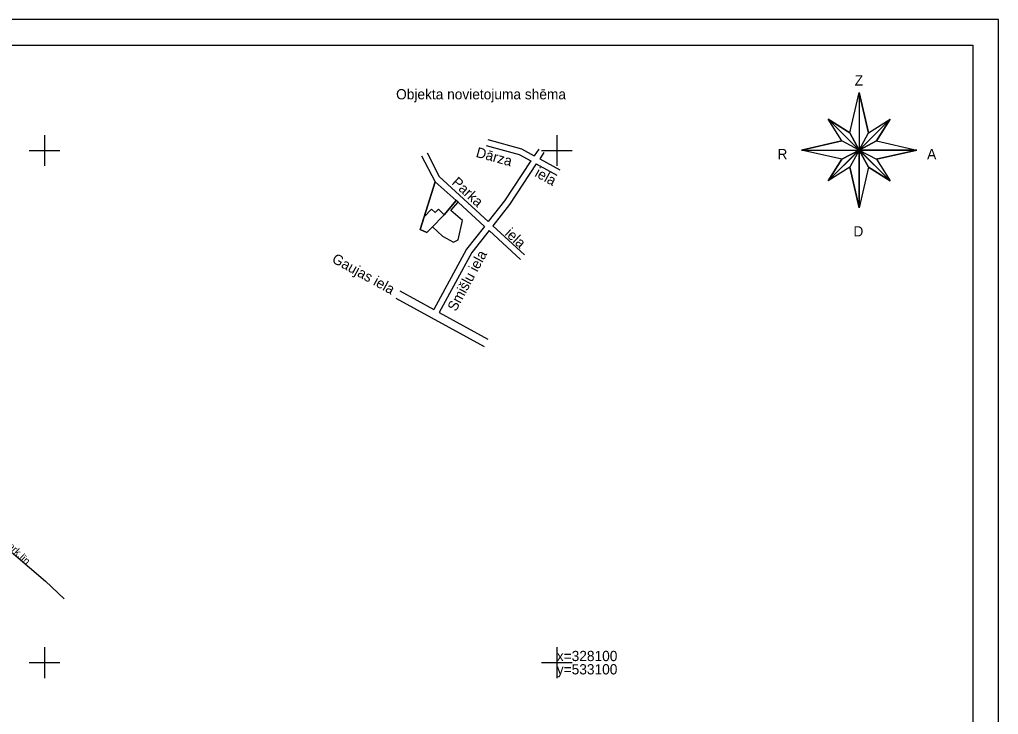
# Model space of a CAD drawing. Extents: x 532933 to 533143, y 328014 to 328163.
# Drawn here: x 533047.6 to 533143.1, y 328094.9 to 328162.8 of the extents above; entities that cross this region are included whole.
import ezdxf

# ---------------------------------------------------------------- set-up
doc = ezdxf.new("R2010")
doc.units = 0
for name, color, linetype in [('APGR_SARK_####_TKST_#', 7, 'Continuous'), ('GEOD_ELEM_####_####_#', 7, 'Continuous'), ('GEOD_KORD_####_TKST_#', 7, 'Continuous'), ('RAMI_PLAN_####_TKST_#', 7, 'Continuous'), ('ROBZ_PROJ_####_####_#', 7, 'Continuous')]:
    doc.layers.add(name, color=color, linetype=linetype)

msp = doc.modelspace()

# ---------------------------------------------------------------- linework, layer by layer
at = {"layer": 'GEOD_ELEM_####_####_#'}
for p, q in [((533050, 328151.5), (533050, 328150)), ((533100, 328151.5), (533100, 328150)), ((533048.5, 328150), (533050, 328150)), ((533050, 328150), (533050, 328148.5)), ((533050, 328150), (533051.5, 328150)), ((533098.5, 328150), (533100, 328150)), ((533100, 328150), (533100, 328148.5)), ((533100, 328150), (533101.5, 328150)), ((533050, 328101.5), (533050, 328100)), ((533100, 328101.5), (533100, 328100)), ((533048.5, 328100), (533050, 328100)), ((533050, 328100), (533050, 328098.5)), ((533050, 328100), (533051.5, 328100)), ((533098.5, 328100), (533100, 328100)), ((533100, 328100), (533100, 328098.5)), ((533100, 328100), (533101.5, 328100))]:
    msp.add_line(p, q, dxfattribs=at)
at = {"layer": 'RAMI_PLAN_####_TKST_#'}
for p, q in [((533143.097, 328162.773), (532933.097, 328162.773)), ((533143.097, 328014.273), (533143.097, 328162.773)), ((532943.097, 328160.273), (533140.597, 328160.273)), ((533140.597, 328160.273), (533140.597, 328016.773)), ((533128.605, 328151.721), (533129.503, 328155.661)), ((533129.503, 328155.661), (533129.503, 328144.411)), ((533129.503, 328155.661), (533130.402, 328151.721)), ((533132.519, 328153.052), (533126.487, 328147.02)), ((533126.487, 328153.052), (533132.519, 328147.02)), ((533127.818, 328150.935), (533126.487, 328153.052)), ((533126.487, 328153.052), (533128.605, 328151.721)), ((533130.402, 328151.721), (533132.519, 328153.052)), ((533132.519, 328153.052), (533131.188, 328150.935)), ((533128.605, 328151.721), (533129.503, 328150.036)), ((533129.503, 328150.036), (533130.402, 328151.721)), ((533123.878, 328150.036), (533127.818, 328150.935)), ((533129.503, 328150.036), (533127.818, 328150.935)), ((533131.188, 328150.935), (533129.503, 328150.036)), ((533131.188, 328150.935), (533135.128, 328150.036)), ((533086.804, 328149.474), (533088.119, 328146.934)), ((533087.336, 328149.75), (533088.521, 328147.463)), ((533123.878, 328150.036), (533135.128, 328150.036)), ((533127.818, 328149.138), (533123.878, 328150.036)), ((533127.818, 328149.138), (533129.503, 328150.036)), ((533129.503, 328150.036), (533128.605, 328148.351)), ((533130.402, 328148.351), (533129.503, 328150.036)), ((533129.503, 328150.036), (533131.188, 328149.138)), ((533135.128, 328150.036), (533131.188, 328149.138)), ((533126.487, 328147.02), (533127.818, 328149.138)), ((533131.188, 328149.138), (533132.519, 328147.02)), ((533128.605, 328148.351), (533126.487, 328147.02)), ((533129.503, 328144.411), (533128.605, 328148.351)), ((533130.402, 328148.351), (533129.503, 328144.411)), ((533132.519, 328147.02), (533130.402, 328148.351)), ((533093.314, 328143.057), (533088.521, 328147.463)), ((533092.942, 328142.584), (533090.362, 328144.955)), ((533096.455, 328139.354), (533093.385, 328142.177)), ((533096.861, 328139.795), (533093.757, 328142.649)), ((533084.672, 328136.29), (533088.006, 328134.461)), ((533084.287, 328135.589), (533092.897, 328130.866)), ((533088.532, 328134.173), (533093.282, 328131.567))]:
    msp.add_line(p, q, dxfattribs=at)
for points in [[(533048.097, 328160.273), (533140.597, 328160.273)], [(533140.597, 328160.273), (533140.597, 328054.273)], [(533129.503, 328150.036), (533130.402, 328151.721), (533129.503, 328155.661), (533129.503, 328150.036)], [(533129.503, 328150.036), (533128.605, 328151.721), (533126.487, 328153.052), (533129.503, 328150.036)], [(533131.188, 328150.935), (533132.519, 328153.052), (533129.503, 328150.036), (533131.188, 328150.935)], [(533093.119, 328150.481), (533096.331, 328149.6), (533097.471, 328148.973)], [(533093.278, 328151.06), (533096.558, 328150.16), (533097.802, 328149.475)], [(533129.503, 328150.036), (533127.818, 328150.935), (533123.878, 328150.036), (533129.503, 328150.036)], [(533098.237, 328150.135), (533097.802, 328149.475)], [(533098.738, 328149.805), (533098.329, 328149.185)], [(533129.503, 328150.036), (533127.818, 328149.138), (533126.487, 328147.02), (533129.503, 328150.036)], [(533129.503, 328150.036), (533128.605, 328148.351), (533129.503, 328144.411), (533129.503, 328150.036)], [(533135.128, 328150.036), (533129.503, 328150.036), (533131.188, 328149.138), (533135.128, 328150.036)], [(533129.503, 328150.036), (533130.402, 328148.351), (533132.519, 328147.02), (533129.503, 328150.036)], [(533097.471, 328148.973), (533094.898, 328145.068), (533093.314, 328143.057)], [(533097.998, 328148.683), (533095.385, 328144.717), (533093.757, 328142.649)], [(533097.998, 328148.683), (533100.002, 328147.579)], [(533098.329, 328149.185), (533100.292, 328148.105)], [(533087.869, 328142.548), (533087.307, 328141.972), (533086.652, 328142.283), (533088.119, 328146.934), (533090.194, 328145.104), (533088.999, 328143.723), (533088.449, 328144.26), (533088.123, 328143.926), (533087.773, 328144.266), (533087.045, 328143.529)], [(533087.869, 328142.548), (533088.836, 328141.634), (533089.925, 328141.047), (533090.363, 328141.258), (533090.801, 328143.162), (533089.651, 328144.133), (533090.362, 328144.955), (533090.194, 328145.104)], [(533088.999, 328143.723), (533088.868, 328143.572), (533087.869, 328142.548)], [(533092.942, 328142.584), (533091.194, 328140.364), (533088.006, 328134.461)], [(533093.385, 328142.177), (533091.697, 328140.033), (533088.532, 328134.173)]]:
    msp.add_lwpolyline(points, dxfattribs=at)
for points in [[(533087.045, 328143.529), (533087.773, 328144.266), (533088.123, 328143.926), (533088.449, 328144.26), (533088.999, 328143.723), (533090.194, 328145.104), (533088.119, 328146.934), (533087.045, 328143.529)], [(533088.868, 328143.572), (533087.869, 328142.548), (533088.836, 328141.634), (533089.925, 328141.047), (533090.363, 328141.258), (533090.801, 328143.162), (533089.651, 328144.133), (533090.362, 328144.955), (533090.194, 328145.104), (533088.999, 328143.723)], [(533086.652, 328142.283), (533087.307, 328141.972), (533087.869, 328142.548), (533088.868, 328143.572), (533088.999, 328143.723), (533088.449, 328144.26), (533088.123, 328143.926), (533087.773, 328144.266), (533087.045, 328143.529), (533087.045, 328143.529)]]:
    msp.add_lwpolyline(points, close=True, dxfattribs=at)
at = {"layer": 'ROBZ_PROJ_####_####_#'}
for p, q in [((533031.763, 328123.637), (533050.089, 328107.938)), ((533050.089, 328107.938), (533051.92, 328106.217))]:
    msp.add_line(p, q, dxfattribs=at)

# ---------------------------------------------------------------- texts
at = {"layer": 'APGR_SARK_####_TKST_#'}
msp.add_text('sark.līn.', height=0.7, rotation=315.80258, dxfattribs=at).set_placement((533046.049, 328111.615))
at = {"layer": 'GEOD_KORD_####_TKST_#'}
for s, p in [('x=328100', (533100, 328100.15)), ('y=533100', (533100, 328098.85))]:
    msp.add_text(s, height=1, dxfattribs=at).set_placement(p)
at = {"layer": 'RAMI_PLAN_####_TKST_#'}
for s, p in [('Z', (533129.073, 328156.328)), ('Objekta novietojuma shēma', (533084.318, 328154.985)), ('R', (533121.533, 328149.145)), ('A', (533136.139, 328149.145)), ('D', (533128.947, 328141.6))]:
    msp.add_text(s, height=1, dxfattribs=at).set_placement(p)
for s, rotation, p in [('Dārza', 344.66431, (533092.042, 328149.379)), ('iela', 331.16603, (533097.77, 328147.518)), ('Parka', 317.40544, (533089.678, 328146.769)), ('iela', 317.40544, (533094.871, 328141.801)), ('Smišlu iela', 61.62838, (533090.151, 328134.216)), ('Gaujas iela', 331.2517, (533077.969, 328139.125))]:
    msp.add_text(s, height=1, rotation=rotation, dxfattribs=at).set_placement(p)

doc.saveas('drawing.dxf')
